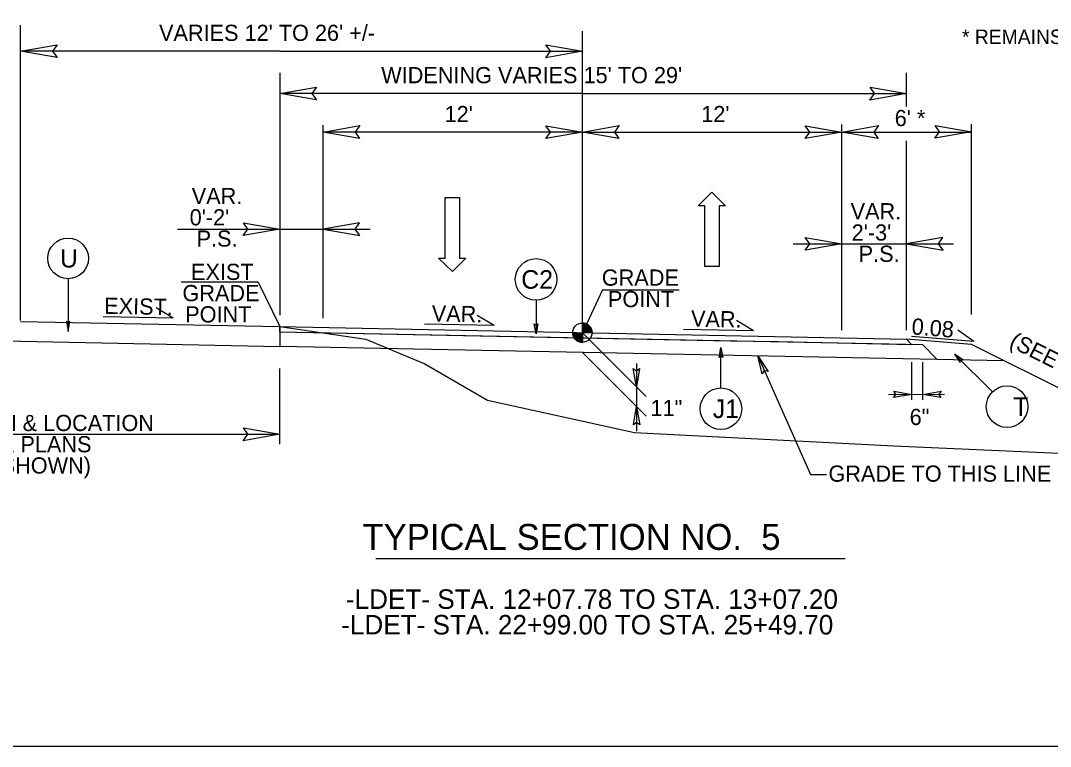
# Model space of a CAD drawing. Extents: x 1548135 to 1549339, y 868664 to 869085.
# Drawn here: x 1548194.74 to 1548242.4, y 868801.82 to 868835.43 of the extents above; entities that cross this region are included whole.
import ezdxf

# ---------------------------------------------------------------- set-up
doc = ezdxf.new("R2010")
doc.units = 0
for name, color, linetype in [('Default', 7, 'Continuous'), ('P_RDY_TC_Pvmt_Asphalt_Base_Course', 7, 'Continuous'), ('Prop Dimension', 7, 'Continuous'), ('Prop Terminator CELL', 7, 'Continuous'), ('Sheet_Data_Field_CELL', 7, 'Continuous'), ('Sheet_Plan', 7, 'Continuous'), ('Typical Curb CELL', 7, 'Continuous'), ('Typical Grade Point Symbol CELL', 7, 'Continuous'), ('Typical Hinge Slope Arterial CELL', 7, 'Continuous'), ('Typical Hinge Slope Interstate CELL', 7, 'Continuous'), ('Typical Pavement Slope Information CELL', 7, 'Continuous'), ('Typical Shoulder Slope CELL', 7, 'Continuous'), ('Typical Shoulder Slope Information CELL', 7, 'Continuous'), ('Typical Terminator CELL', 7, 'Continuous'), ('Typical Text Centerline CELL', 7, 'Continuous'), ('Typical Text General CELL', 7, 'Continuous'), ('Typical Text Grade Point CELL', 7, 'Continuous'), ('z - Construction', 7, 'Continuous')]:
    doc.layers.add(name, color=color, linetype=linetype)

msp = doc.modelspace()

# ---------------------------------------------------------------- linework, layer by layer
at = {"layer": 'Default'}
msp.add_lwpolyline([(1548135.05, 868911.824), (1548305.05, 868911.824), (1548305.05, 868801.824), (1548135.05, 868801.824)], close=True, dxfattribs=at)
at = {"layer": 'P_RDY_TC_Pvmt_Asphalt_Base_Course'}
for points in [[(1548196.425, 868833.715), (1548194.737, 868834.006), (1548196.434, 868834.306), (1548196.218, 868834.006)], [(1548219.05, 868834.297), (1548220.737, 868834.006), (1548219.04, 868833.706), (1548219.256, 868834.006)], [(1548208.425, 868831.756), (1548206.737, 868832.047), (1548208.434, 868832.347), (1548208.218, 868832.047)], [(1548234.05, 868832.338), (1548235.737, 868832.047), (1548234.04, 868831.747), (1548234.256, 868832.047)], [(1548210.425, 868829.974), (1548208.737, 868830.265), (1548210.434, 868830.565), (1548210.218, 868830.265)], [(1548219.05, 868830.555), (1548220.737, 868830.265), (1548219.04, 868829.965), (1548219.256, 868830.265)], [(1548222.425, 868829.974), (1548220.737, 868830.265), (1548222.434, 868830.565), (1548222.218, 868830.265)], [(1548231.05, 868830.555), (1548232.737, 868830.265), (1548231.04, 868829.965), (1548231.256, 868830.265)], [(1548234.425, 868829.974), (1548232.737, 868830.265), (1548234.434, 868830.565), (1548234.218, 868830.265)], [(1548237.061, 868830.573), (1548238.748, 868830.282), (1548237.051, 868829.982), (1548237.267, 868830.282)], [(1548205.05, 868826.067), (1548206.737, 868825.776), (1548205.04, 868825.476), (1548205.256, 868825.776)], [(1548210.425, 868826.067), (1548208.737, 868825.776), (1548210.434, 868825.476), (1548210.218, 868825.776)], [(1548231.05, 868825.382), (1548232.737, 868825.091), (1548231.04, 868824.791), (1548231.256, 868825.091)], [(1548237.425, 868825.382), (1548235.737, 868825.091), (1548237.434, 868824.791), (1548237.218, 868825.091)], [(1548205.05, 868816.567), (1548206.737, 868816.277), (1548205.04, 868815.977), (1548205.256, 868816.277)]]:
    msp.add_lwpolyline(points, close=True, dxfattribs=at)
at = {"layer": 'Prop Dimension'}
msp.add_line((1548249.386, 868815.108), (1548238.748, 868820.427), dxfattribs=at)
at = {"layer": 'Prop Terminator CELL'}
msp.add_lwpolyline([(1548206.737, 868821.258), (1548235.737, 868820.678), (1548235.988, 868820.423), (1548231.144, 868820.52), (1548229.817, 868820.547), (1548227.59, 868820.591), (1548206.737, 868821.008), (1548206.737, 868821.008)], close=True, dxfattribs=at)
at = {"layer": 'Sheet_Plan'}
msp.add_line((1548238.748, 868820.427), (1548235.737, 868820.678), dxfattribs=at)
at = {"layer": 'Typical Curb CELL'}
for p, q in [((1548220.737, 868820.978), (1548220.737, 868821.426)), ((1548220.289, 868820.978), (1548220.737, 868820.978)), ((1548220.736, 868820.531), (1548220.737, 868820.978)), ((1548220.737, 868820.978), (1548220.736, 868820.531)), ((1548221.185, 868820.978), (1548220.737, 868820.978))]:
    msp.add_line(p, q, dxfattribs=at)
for points in [[(1548220.741, 868821.426), (1548220.741, 868821.426), (1548220.741, 868820.978)], [(1548220.75, 868821.426), (1548220.75, 868820.978)], [(1548220.759, 868821.425), (1548220.759, 868820.978)], [(1548220.768, 868821.425), (1548220.768, 868820.978)], [(1548220.777, 868821.424), (1548220.777, 868820.978)], [(1548220.786, 868821.423), (1548220.786, 868820.978)], [(1548220.795, 868821.422), (1548220.795, 868820.978)], [(1548220.804, 868821.421), (1548220.804, 868820.978)], [(1548220.813, 868821.42), (1548220.813, 868820.978)], [(1548220.822, 868821.418), (1548220.822, 868820.978)], [(1548220.831, 868821.416), (1548220.831, 868820.978)], [(1548220.84, 868821.414), (1548220.84, 868820.978)], [(1548220.848, 868821.412), (1548220.848, 868820.978)], [(1548220.857, 868821.409), (1548220.857, 868820.978)], [(1548220.866, 868821.407), (1548220.866, 868820.978)], [(1548220.875, 868821.404), (1548220.875, 868820.978)], [(1548220.884, 868821.401), (1548220.884, 868820.978)], [(1548220.893, 868821.398), (1548220.893, 868820.978)], [(1548220.902, 868821.394), (1548220.902, 868820.978)], [(1548220.911, 868821.39), (1548220.911, 868820.978)], [(1548220.92, 868821.386), (1548220.92, 868820.978)], [(1548220.929, 868821.382), (1548220.929, 868820.978)], [(1548220.938, 868821.378), (1548220.938, 868820.978)], [(1548220.947, 868821.373), (1548220.947, 868820.978)], [(1548220.292, 868820.978), (1548220.292, 868820.929)], [(1548220.3, 868820.978), (1548220.3, 868820.877)], [(1548220.309, 868820.978), (1548220.309, 868820.845)], [(1548220.318, 868820.978), (1548220.318, 868820.818)], [(1548220.327, 868820.978), (1548220.327, 868820.797)], [(1548220.336, 868820.978), (1548220.336, 868820.778)], [(1548220.345, 868820.978), (1548220.345, 868820.761)], [(1548220.354, 868820.978), (1548220.354, 868820.745)], [(1548220.363, 868820.978), (1548220.363, 868820.731)], [(1548220.372, 868820.978), (1548220.372, 868820.719)], [(1548220.381, 868820.978), (1548220.381, 868820.707)], [(1548220.39, 868820.978), (1548220.39, 868820.696)], [(1548220.399, 868820.978), (1548220.399, 868820.685)], [(1548220.408, 868820.978), (1548220.408, 868820.675)], [(1548220.417, 868820.978), (1548220.417, 868820.665)], [(1548220.426, 868820.978), (1548220.426, 868820.656)], [(1548220.435, 868820.978), (1548220.435, 868820.648)], [(1548220.444, 868820.978), (1548220.444, 868820.64)], [(1548220.453, 868820.978), (1548220.453, 868820.632)], [(1548220.462, 868820.978), (1548220.462, 868820.625)], [(1548220.471, 868820.978), (1548220.471, 868820.618)], [(1548220.479, 868820.978), (1548220.479, 868820.612)], [(1548220.488, 868820.978), (1548220.488, 868820.606)], [(1548220.497, 868820.978), (1548220.497, 868820.6)], [(1548220.506, 868820.978), (1548220.506, 868820.594)], [(1548220.515, 868820.978), (1548220.515, 868820.589)], [(1548220.524, 868820.978), (1548220.524, 868820.584)], [(1548220.533, 868820.978), (1548220.533, 868820.579)], [(1548220.542, 868820.978), (1548220.542, 868820.575)], [(1548220.551, 868820.978), (1548220.551, 868820.571)], [(1548220.56, 868820.978), (1548220.56, 868820.567)], [(1548220.569, 868820.978), (1548220.569, 868820.563)], [(1548220.578, 868820.978), (1548220.578, 868820.559)], [(1548220.587, 868820.978), (1548220.587, 868820.556)], [(1548220.596, 868820.978), (1548220.596, 868820.553)], [(1548220.605, 868820.978), (1548220.605, 868820.55)], [(1548220.614, 868820.978), (1548220.614, 868820.548)], [(1548220.623, 868820.978), (1548220.623, 868820.545)], [(1548220.632, 868820.978), (1548220.632, 868820.543)], [(1548220.641, 868820.978), (1548220.641, 868820.541)], [(1548220.65, 868820.978), (1548220.65, 868820.539)], [(1548220.658, 868820.978), (1548220.658, 868820.537)], [(1548220.667, 868820.978), (1548220.667, 868820.537)], [(1548220.676, 868820.978), (1548220.676, 868820.535)], [(1548220.685, 868820.978), (1548220.685, 868820.534)], [(1548220.694, 868820.978), (1548220.694, 868820.533)], [(1548220.703, 868820.978), (1548220.703, 868820.532)], [(1548220.712, 868820.978), (1548220.712, 868820.532)], [(1548220.721, 868820.978), (1548220.721, 868820.531)], [(1548220.73, 868820.978), (1548220.73, 868820.531), (1548220.73, 868820.531)], [(1548220.956, 868821.368), (1548220.956, 868820.978)], [(1548220.965, 868821.363), (1548220.965, 868820.978)], [(1548220.974, 868821.358), (1548220.974, 868820.978)], [(1548220.983, 868821.352), (1548220.983, 868820.978)], [(1548220.992, 868821.346), (1548220.992, 868820.978)], [(1548221.001, 868821.339), (1548221.001, 868820.978)], [(1548221.01, 868821.333), (1548221.01, 868820.978)], [(1548221.019, 868821.326), (1548221.019, 868820.978)], [(1548221.028, 868821.318), (1548221.028, 868820.978)], [(1548221.036, 868821.31), (1548221.036, 868820.978)], [(1548221.045, 868821.302), (1548221.045, 868820.978)], [(1548221.054, 868821.293), (1548221.054, 868820.978)], [(1548221.063, 868821.284), (1548221.063, 868820.978)], [(1548221.072, 868821.275), (1548221.072, 868820.978)], [(1548221.081, 868821.264), (1548221.081, 868820.978)], [(1548221.09, 868821.253), (1548221.09, 868820.978)], [(1548221.099, 868821.241), (1548221.099, 868820.978)], [(1548221.108, 868821.228), (1548221.108, 868820.978)], [(1548221.117, 868821.214), (1548221.117, 868820.978)], [(1548221.126, 868821.199), (1548221.126, 868820.978)], [(1548221.135, 868821.183), (1548221.135, 868820.978)], [(1548221.144, 868821.164), (1548221.144, 868820.978)], [(1548221.153, 868821.143), (1548221.153, 868820.978)], [(1548221.162, 868821.118), (1548221.162, 868820.978)], [(1548221.171, 868821.088), (1548221.171, 868820.978)], [(1548221.18, 868821.042), (1548221.18, 868820.978)]]:
    msp.add_lwpolyline(points, dxfattribs=at)
msp.add_circle((1548220.737, 868820.978), 0.448, dxfattribs=at)
for start, end in [(359.9905, 89.9905), (179.9905, 269.9905)]:
    msp.add_arc((1548220.737, 868820.978), 0.448, start, end, dxfattribs=at)
at = {"layer": 'Typical Grade Point Symbol CELL'}
for p, q in [((1548194.737, 868821.538), (1548194.737, 868835.209)), ((1548220.737, 868820.978), (1548220.737, 868834.929)), ((1548206.737, 868834.006), (1548194.737, 868834.006)), ((1548206.737, 868834.006), (1548220.737, 868834.006)), ((1548206.737, 868833), (1548206.737, 868821.786)), ((1548235.737, 868831.454), (1548235.737, 868833)), ((1548220.737, 868832.047), (1548206.737, 868832.047)), ((1548220.737, 868832.047), (1548235.737, 868832.047)), ((1548208.737, 868821.645), (1548208.737, 868830.59)), ((1548232.737, 868821.098), (1548232.737, 868830.61)), ((1548238.748, 868821.817), (1548238.748, 868830.628)), ((1548220.737, 868830.265), (1548208.737, 868830.265)), ((1548220.737, 868830.265), (1548238.748, 868830.265)), ((1548235.737, 868821.098), (1548235.737, 868829.859)), ((1548201.993, 868825.776), (1548210.918, 868825.776)), ((1548230.487, 868825.091), (1548237.918, 868825.091))]:
    msp.add_line(p, q, dxfattribs=at)
at = {"layer": 'Typical Hinge Slope Arterial CELL'}
for p, q in [((1548205.729, 868823.321), (1548202.172, 868823.321)), ((1548221.661, 868822.964), (1548225.218, 868822.964))]:
    msp.add_line(p, q, dxfattribs=at)
at = {"layer": 'Typical Hinge Slope Interstate CELL'}
for p, q in [((1548196.934, 868823.475), (1548196.934, 868821.039)), ((1548218.593, 868822.482), (1548218.593, 868820.92)), ((1548194.737, 868821.498), (1548206.737, 868821.258)), ((1548206.737, 868821.258), (1548206.737, 868820.341)), ((1548236.488, 868820.413), (1548206.737, 868821.008)), ((1548223.689, 868818.027), (1548220.737, 868820.978)), ((1548194.737, 868820.581), (1548182.737, 868820.341)), ((1548194.737, 868820.581), (1548206.737, 868820.341)), ((1548240.261, 868819.671), (1548206.737, 868820.341)), ((1548223.689, 868817.11), (1548220.737, 868820.061)), ((1548227.149, 868818.418), (1548227.149, 868820.296)), ((1548239.712, 868818.233), (1548237.953, 868819.99)), ((1548223.242, 868819.552), (1548223.244, 868816.42)), ((1548235.988, 868817.867), (1548235.988, 868819.617)), ((1548236.488, 868817.867), (1548236.488, 868819.617)), ((1548234.91, 868818.122), (1548237.499, 868818.124))]:
    msp.add_line(p, q, dxfattribs=at)
for points in [[(1548196.855, 868821.499), (1548196.934, 868821.039), (1548197.016, 868821.501), (1548196.934, 868821.443)], [(1548218.673, 868821.388), (1548218.593, 868820.92), (1548218.509, 868821.391), (1548218.593, 868821.331)], [(1548227.069, 868819.827), (1548227.149, 868820.296), (1548227.233, 868819.825), (1548227.149, 868819.885)], [(1548238.342, 868819.716), (1548237.953, 868819.99), (1548238.228, 868819.598), (1548238.244, 868819.7)], [(1548229.06, 868819.069), (1548228.851, 868819.899), (1548229.332, 868819.184), (1548229.151, 868819.222)], [(1548223.387, 868819.317), (1548223.242, 868818.473), (1548223.092, 868819.322), (1548223.242, 868819.214)], [(1548235.144, 868818.268), (1548235.988, 868818.123), (1548235.14, 868817.973), (1548235.247, 868818.123)], [(1548237.332, 868817.978), (1548236.488, 868818.123), (1548237.337, 868818.273), (1548237.229, 868818.123)], [(1548223.098, 868816.712), (1548223.243, 868817.555), (1548223.393, 868816.707), (1548223.243, 868816.815)]]:
    msp.add_lwpolyline(points, close=True, dxfattribs=at)
for points in [[(1548206.737, 868821.258), (1548210.718, 868820.675), (1548213.45, 868819.529), (1548216.353, 868817.848), (1548223.146, 868816.357), (1548235.151, 868815.732), (1548249.386, 868815.108)], [(1548228.851, 868819.899), (1548231.287, 868814.409), (1548232.038, 868814.409)]]:
    msp.add_lwpolyline(points, dxfattribs=at)
for centre, radius in [((1548196.934, 868824.417), 0.942), ((1548218.593, 868823.443), 0.962), ((1548240.391, 868817.553), 0.962), ((1548227.149, 868817.456), 0.962)]:
    msp.add_circle(centre, radius, dxfattribs=at)
at = {"layer": 'Typical Pavement Slope Information CELL'}
for p, q in [((1548201.792, 868821.654), (1548201.009, 868822.127)), ((1548201.792, 868821.654), (1548198.563, 868821.718)), ((1548216.653, 868821.306), (1548213.424, 868821.37)), ((1548216.653, 868821.306), (1548215.87, 868821.779)), ((1548228.653, 868821.066), (1548227.87, 868821.539)), ((1548228.653, 868821.066), (1548225.424, 868821.13)), ((1548238.859, 868820.567), (1548238.108, 868821.089)), ((1548238.859, 868820.567), (1548235.976, 868820.807))]:
    msp.add_line(p, q, dxfattribs=at)
at = {"layer": 'Typical Shoulder Slope CELL'}
for p, q in [((1548205.729, 868823.321), (1548206.737, 868821.258)), ((1548221.661, 868822.964), (1548220.737, 868820.978))]:
    msp.add_line(p, q, dxfattribs=at)
at = {"layer": 'Typical Shoulder Slope Information CELL'}
for p, q in [((1548214.384, 868824.434), (1548214.384, 868827.234)), ((1548214.384, 868827.234), (1548215.044, 868827.234)), ((1548215.044, 868827.234), (1548215.044, 868824.434)), ((1548226.101, 868826.848), (1548226.721, 868827.478)), ((1548226.721, 868827.478), (1548227.361, 868826.848)), ((1548226.401, 868826.848), (1548226.101, 868826.848)), ((1548226.401, 868824.048), (1548226.401, 868826.848)), ((1548227.361, 868826.848), (1548227.061, 868826.848)), ((1548227.061, 868826.848), (1548227.061, 868824.048)), ((1548214.724, 868823.804), (1548214.084, 868824.434)), ((1548214.084, 868824.434), (1548214.384, 868824.434)), ((1548215.344, 868824.434), (1548214.724, 868823.804)), ((1548215.044, 868824.434), (1548215.344, 868824.434)), ((1548227.061, 868824.048), (1548226.401, 868824.048))]:
    msp.add_line(p, q, dxfattribs=at)
at = {"layer": 'Typical Terminator CELL'}
for p, q in [((1548206.737, 868815.822), (1548206.737, 868819.325)), ((1548182.737, 868816.277), (1548206.737, 868816.277)), ((1548211.185, 868810.521), (1548232.906, 868810.521))]:
    msp.add_line(p, q, dxfattribs=at)
at = {"layer": 'Typical Text Grade Point CELL'}
for p, q in [((1548206.737, 868821.258), (1548235.737, 868820.678)), ((1548235.737, 868820.678), (1548235.988, 868820.423)), ((1548236.488, 868820.413), (1548237.156, 868819.733))]:
    msp.add_line(p, q, dxfattribs=at)

# ---------------------------------------------------------------- texts
at = {"layer": 'Sheet_Data_Field_CELL'}
msp.add_text('(SEE CROSS SECTIONS)', height=0.75, rotation=333.434, dxfattribs=at).set_placement((1548240.447, 868820.36))
at = {"layer": 'Typical Hinge Slope Arterial CELL'}
msp.add_text('  TYPICAL SECTION NO.  5', height=1.2, dxfattribs=at).set_placement((1548209.666, 868810.923))
at = {"layer": 'Typical Hinge Slope Interstate CELL'}
for s, height, p in [('U', 0.844, (1548196.567, 868823.995)), ('C2', 0.8608, (1548217.907, 868823.013)), ('11"', 0.75, (1548223.889, 868817.115)), ('J1', 0.8608, (1548226.771, 868817.026)), ('T', 0.861, (1548240.674, 868817.123)), ('6"', 0.75, (1548235.883, 868816.703)), ('GRADE TO THIS LINE', 0.75, (1548232.125, 868814.079))]:
    msp.add_text(s, height=height, dxfattribs=at).set_placement(p)
at = {"layer": 'Typical Pavement Slope Information CELL'}
for s, p in [('EXIST.', (1548198.6, 868821.853)), ('VAR.', (1548213.759, 868821.499)), ('VAR.', (1548225.759, 868821.259))]:
    msp.add_text(s, height=0.75, rotation=358.8544, dxfattribs=at).set_placement(p)
at = {"layer": 'Typical Shoulder Slope CELL'}
for s, p in [("VARIES 12' TO 26' +/-", (1548201.144, 868834.485)), ("WIDENING VARIES 15' TO 29'", (1548211.428, 868832.526)), ("12'", (1548214.36, 868830.725)), ("12'", (1548226.237, 868830.725)), ("6' *", (1548235.192, 868830.539)), ('EXIST', (1548202.624, 868823.418)), ('GRADE', (1548221.636, 868823.154)), ('GRADE', (1548202.228, 868822.435)), ('POINT', (1548221.92, 868822.16)), ('POINT', (1548202.355, 868821.452)), ('VAR. WIDTH & LOCATION', (1548188.649, 868816.423)), ('SEE PLANS', (1548192.445, 868815.44)), ("(24' SHOWN)", (1548191.895, 868814.457))]:
    msp.add_text(s, height=0.75, dxfattribs=at).set_placement(p)
at = {"layer": 'Typical Text Centerline CELL'}
for s, p in [('VAR. ', (1548202.659, 868826.929)), ("0'-2'", (1548202.562, 868825.945)), ('VAR. ', (1548233.151, 868826.224)), ('P.S.', (1548202.883, 868824.962)), ("2'-3'", (1548233.202, 868825.241)), ('P.S.', (1548233.523, 868824.257))]:
    msp.add_text(s, height=0.75, dxfattribs=at).set_placement(p)
at = {"layer": 'Typical Text General CELL'}
for s, height, p in [("* REMAINS 6' W/ GUARDRAIL", 0.66824, (1548238.304, 868834.342)), ('-LDET- STA. 12+07.78 TO STA. 13+07.20', 0.90387, (1548209.791, 868808.191)), ('-LDET- STA. 22+99.00 TO STA. 25+49.70', 0.90387, (1548209.574, 868807.006))]:
    msp.add_text(s, height=height, dxfattribs=at).set_placement(p)
at = {"layer": 'z - Construction'}
msp.add_text('0.08', height=0.75, rotation=355.2385, dxfattribs=at).set_placement((1548235.952, 868820.905))

doc.saveas('drawing.dxf')
